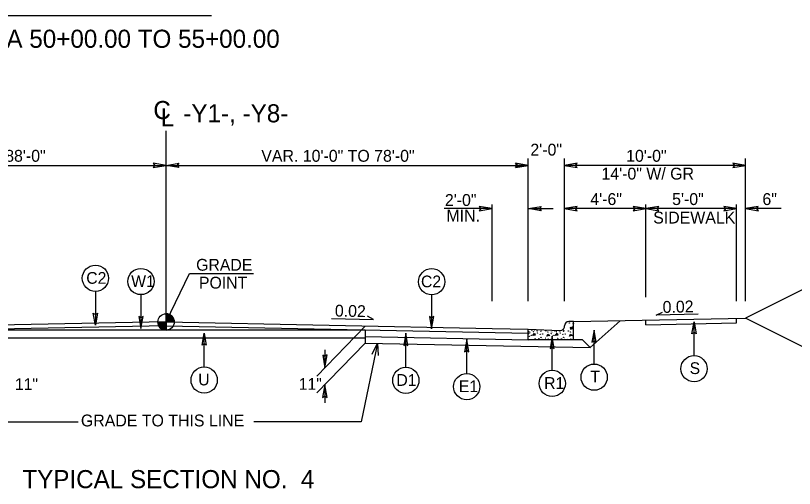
# Model space of a CAD drawing. Extents: x 1901670 to 1902225, y 193498 to 194278.
# Drawn here: x 1902030.87 to 1902073.88, y 193992.53 to 194018.66 of the extents above; entities that cross this region are included whole.
import ezdxf

# ---------------------------------------------------------------- set-up
doc = ezdxf.new("R2010")
doc.units = 0
for name, color, linetype in [('Old_Level_1', 7, 'Continuous'), ('Old_Level_11', 7, 'Continuous'), ('Old_Level_2', 7, 'Continuous'), ('Old_Level_20', 7, 'Continuous'), ('Prop Dimension', 7, 'Continuous'), ('Typical Curb CELL', 7, 'Continuous'), ('Typical Pavement Slope CELL', 7, 'Continuous'), ('Typical Terminator CELL', 7, 'Continuous'), ('Typical Text Grade Point CELL', 7, 'Continuous')]:
    doc.layers.add(name, color=color, linetype=linetype)

# ---------------------------------------------------------------- blocks, each defined once
blk = doc.blocks.new('TERMINATOR')
at = {"layer": 'Typical Terminator CELL'}
blk.add_lwpolyline([(-0.469, 0.081), (0, 0), (-0.471, -0.083), (-0.411, 0)], close=True, dxfattribs=at)

msp = doc.modelspace()

# ---------------------------------------------------------------- linework, layer by layer
at = {"layer": 'Old_Level_1'}
for p, q in [((1902039.184, 194001.732), (1902039.184, 194012.291)), ((1902039.184, 194001.732), (1902039.184, 194002.182)), ((1902066.255, 194002.109), (1902066.588, 194002.276)), ((1902068.57, 194002.158), (1902066.255, 194002.109)), ((1902039.184, 194001.732), (1902019.184, 194001.332)), ((1902038.734, 194001.732), (1902039.184, 194001.732)), ((1902039.183, 194001.282), (1902039.184, 194001.732)), ((1902039.184, 194001.732), (1902039.183, 194001.282)), ((1902039.634, 194001.732), (1902039.184, 194001.732)), ((1902039.184, 194001.732), (1902057.184, 194001.372)), ((1902048.323, 194001.923), (1902050.638, 194001.874)), ((1902050.638, 194001.874), (1902050.305, 194002.041)), ((1902064.265, 194001.8), (1902062.607, 194000.316)), ((1902039.184, 194001.513), (1902019.184, 194001.113)), ((1902028.186, 194001.293), (1902050.182, 194001.293)), ((1902039.184, 194001.513), (1902059.184, 194001.113)), ((1902050.184, 194001.499), (1902047.512, 193998.739)), ((1902050.182, 194001.293), (1902050.182, 194000.564)), ((1902057.184, 194001.372), (1902059.184, 194001.332)), ((1902028.186, 194000.846), (1902050.182, 194000.846)), ((1902050.182, 194000.929), (1902059.184, 194000.749)), ((1902050.182, 194000.564), (1902047.512, 193997.806)), ((1902050.182, 194000.564), (1902062.607, 194000.316)), ((1902062.184, 194000.739), (1902061.684, 194000.749)), ((1902062.184, 194000.739), (1902062.607, 194000.316)), ((1902047.958, 194000.199), (1902047.958, 193999.199)), ((1902047.955, 193998.264), (1902047.955, 193997.264))]:
    msp.add_line(p, q, dxfattribs=at)
for points in [[(1902039.188, 194002.182), (1902039.188, 194002.182), (1902039.188, 194001.732)], [(1902039.197, 194002.182), (1902039.197, 194001.732)], [(1902039.206, 194002.181), (1902039.206, 194001.732)], [(1902039.215, 194002.181), (1902039.215, 194001.732)], [(1902039.224, 194002.18), (1902039.224, 194001.732)], [(1902039.233, 194002.179), (1902039.233, 194001.732)], [(1902039.242, 194002.178), (1902039.242, 194001.732)], [(1902039.251, 194002.177), (1902039.251, 194001.732)], [(1902039.26, 194002.176), (1902039.26, 194001.732)], [(1902039.269, 194002.174), (1902039.269, 194001.732)], [(1902039.278, 194002.172), (1902039.278, 194001.732)], [(1902039.287, 194002.17), (1902039.287, 194001.732)], [(1902039.296, 194002.168), (1902039.296, 194001.732)], [(1902039.305, 194002.165), (1902039.305, 194001.732)], [(1902039.314, 194002.163), (1902039.314, 194001.732)], [(1902039.323, 194002.16), (1902039.323, 194001.732)], [(1902039.332, 194002.157), (1902039.332, 194001.732)], [(1902039.341, 194002.154), (1902039.341, 194001.732)], [(1902039.35, 194002.15), (1902039.35, 194001.732)], [(1902039.359, 194002.146), (1902039.359, 194001.732)], [(1902039.368, 194002.142), (1902039.368, 194001.732)], [(1902039.377, 194002.138), (1902039.377, 194001.732)], [(1902039.386, 194002.134), (1902039.386, 194001.732)], [(1902039.395, 194002.129), (1902039.395, 194001.732)], [(1902039.404, 194002.124), (1902039.404, 194001.732)], [(1902039.413, 194002.119), (1902039.413, 194001.732)], [(1902039.422, 194002.114), (1902039.422, 194001.732)], [(1902039.431, 194002.108), (1902039.431, 194001.732)], [(1902039.44, 194002.102), (1902039.44, 194001.732)], [(1902039.449, 194002.095), (1902039.449, 194001.732)], [(1902039.458, 194002.089), (1902039.458, 194001.732)], [(1902038.736, 194001.732), (1902038.736, 194001.683)], [(1902038.745, 194001.732), (1902038.745, 194001.63)], [(1902038.754, 194001.732), (1902038.754, 194001.598)], [(1902038.763, 194001.732), (1902038.763, 194001.571)], [(1902038.772, 194001.732), (1902038.772, 194001.55)], [(1902038.781, 194001.732), (1902038.781, 194001.531)], [(1902038.79, 194001.732), (1902038.79, 194001.514)], [(1902038.799, 194001.732), (1902038.799, 194001.498)], [(1902038.808, 194001.732), (1902038.808, 194001.484)], [(1902038.817, 194001.732), (1902038.817, 194001.471)], [(1902038.826, 194001.732), (1902038.826, 194001.459)], [(1902038.835, 194001.732), (1902038.835, 194001.448)], [(1902038.844, 194001.732), (1902038.844, 194001.437)], [(1902038.853, 194001.732), (1902038.853, 194001.427)], [(1902038.862, 194001.732), (1902038.862, 194001.417)], [(1902038.871, 194001.732), (1902038.871, 194001.408)], [(1902038.88, 194001.732), (1902038.88, 194001.4)], [(1902038.889, 194001.732), (1902038.889, 194001.392)], [(1902038.898, 194001.732), (1902038.898, 194001.384)], [(1902038.907, 194001.732), (1902038.907, 194001.377)], [(1902038.916, 194001.732), (1902038.916, 194001.37)], [(1902038.925, 194001.732), (1902038.925, 194001.364)], [(1902038.934, 194001.732), (1902038.934, 194001.358)], [(1902038.943, 194001.732), (1902038.943, 194001.352)], [(1902038.952, 194001.732), (1902038.952, 194001.346)], [(1902038.961, 194001.732), (1902038.961, 194001.341)], [(1902038.97, 194001.732), (1902038.97, 194001.336)], [(1902038.979, 194001.732), (1902038.979, 194001.331)], [(1902038.988, 194001.732), (1902038.988, 194001.327)], [(1902038.997, 194001.732), (1902038.997, 194001.323)], [(1902039.006, 194001.732), (1902039.006, 194001.319)], [(1902039.015, 194001.732), (1902039.015, 194001.315)], [(1902039.024, 194001.732), (1902039.024, 194001.311)], [(1902039.033, 194001.732), (1902039.033, 194001.308)], [(1902039.042, 194001.732), (1902039.042, 194001.305)], [(1902039.051, 194001.732), (1902039.051, 194001.302)], [(1902039.06, 194001.732), (1902039.06, 194001.3)], [(1902039.069, 194001.732), (1902039.069, 194001.297)], [(1902039.078, 194001.732), (1902039.078, 194001.295)], [(1902039.087, 194001.732), (1902039.087, 194001.293)], [(1902039.096, 194001.732), (1902039.096, 194001.291)], [(1902039.105, 194001.732), (1902039.105, 194001.289)], [(1902039.114, 194001.732), (1902039.114, 194001.288)], [(1902039.123, 194001.732), (1902039.123, 194001.286)], [(1902039.132, 194001.732), (1902039.132, 194001.285)], [(1902039.141, 194001.732), (1902039.141, 194001.284)], [(1902039.15, 194001.732), (1902039.15, 194001.283)], [(1902039.159, 194001.732), (1902039.159, 194001.283)], [(1902039.168, 194001.732), (1902039.168, 194001.282)], [(1902039.177, 194001.732), (1902039.177, 194001.282), (1902039.177, 194001.282)], [(1902039.467, 194002.082), (1902039.467, 194001.732)], [(1902039.476, 194002.074), (1902039.476, 194001.732)], [(1902039.485, 194002.066), (1902039.485, 194001.732)], [(1902039.494, 194002.058), (1902039.494, 194001.732)], [(1902039.503, 194002.049), (1902039.503, 194001.732)], [(1902039.512, 194002.04), (1902039.512, 194001.732)], [(1902039.521, 194002.03), (1902039.521, 194001.732)], [(1902039.53, 194002.019), (1902039.53, 194001.732)], [(1902039.539, 194002.008), (1902039.539, 194001.732)], [(1902039.548, 194001.996), (1902039.548, 194001.732)], [(1902039.557, 194001.983), (1902039.557, 194001.732)], [(1902039.566, 194001.969), (1902039.566, 194001.732)], [(1902039.575, 194001.954), (1902039.575, 194001.732)], [(1902039.584, 194001.938), (1902039.584, 194001.732)], [(1902039.593, 194001.919), (1902039.593, 194001.732)], [(1902039.602, 194001.898), (1902039.602, 194001.732)], [(1902039.611, 194001.873), (1902039.611, 194001.732)], [(1902039.62, 194001.842), (1902039.62, 194001.732)], [(1902039.629, 194001.796), (1902039.629, 194001.732)], [(1902050.862, 194000.551), (1902049.953, 193996.205)], [(1902050.569, 193999.942), (1902050.862, 194000.551), (1902050.89, 193999.875)], [(1902028.415, 193996.205), (1902034.331, 193996.205)], [(1902049.953, 193996.205), (1902044.037, 193996.205)]]:
    msp.add_lwpolyline(points, dxfattribs=at)
msp.add_circle((1902039.184, 194001.732), 0.45, dxfattribs=at)
for start, end in [(359.9905, 89.9905), (179.9905, 269.9905)]:
    msp.add_arc((1902039.184, 194001.732), 0.45, start, end, dxfattribs=at)
at = {"layer": 'Old_Level_11'}
for p, q in [((1902021.954, 194018.656), (1902041.697, 194018.656)), ((1902035.284, 194003.419), (1902035.284, 194001.545)), ((1902037.795, 194003.238), (1902037.795, 194001.364)), ((1902053.85, 194003.225), (1902053.85, 194001.351)), ((1902068.338, 193999.872), (1902068.338, 194001.746)), ((1902062.823, 193999.406), (1902062.823, 194001.28)), ((1902041.287, 193999.244), (1902041.287, 194001.118)), ((1902052.425, 193999.23), (1902052.425, 194001.104)), ((1902060.507, 193999.061), (1902060.507, 194000.935)), ((1902055.784, 193998.881), (1902055.784, 194000.755))]:
    msp.add_line(p, q, dxfattribs=at)
for points in [[(1902035.4, 194002.217), (1902035.284, 194001.545), (1902035.165, 194002.22), (1902035.284, 194002.134)], [(1902037.68, 194002.036), (1902037.795, 194001.364), (1902037.915, 194002.039), (1902037.795, 194001.953)], [(1902053.734, 194002.023), (1902053.85, 194001.351), (1902053.969, 194002.026), (1902053.85, 194001.941)], [(1902068.223, 194001.074), (1902068.338, 194001.746), (1902068.458, 194001.071), (1902068.338, 194001.156)], [(1902062.938, 194000.609), (1902062.823, 194001.28), (1902062.703, 194000.605), (1902062.823, 194000.691)], [(1902041.172, 194000.447), (1902041.287, 194001.118), (1902041.407, 194000.443), (1902041.287, 194000.529)], [(1902052.541, 194000.432), (1902052.425, 194001.104), (1902052.306, 194000.429), (1902052.425, 194000.514)], [(1902060.622, 194000.263), (1902060.507, 194000.935), (1902060.387, 194000.26), (1902060.507, 194000.345)], [(1902055.9, 194000.084), (1902055.784, 194000.755), (1902055.665, 194000.08), (1902055.784, 194000.166)]]:
    msp.add_lwpolyline(points, close=True, dxfattribs=at)
for centre in [(1902035.284, 194004.144), (1902037.795, 194003.963), (1902053.85, 194003.951), (1902068.338, 193999.146), (1902041.287, 193998.519), (1902052.425, 193998.505), (1902062.823, 193998.681), (1902055.784, 193998.156), (1902060.507, 193998.336)]:
    msp.add_circle(centre, 0.725, dxfattribs=at)
at = {"layer": 'Prop Dimension'}
for p, q in [((1902059.184, 194002.87), (1902059.184, 194010.752)), ((1902059.184, 194002.87), (1902059.184, 194010.712)), ((1902061.184, 194002.87), (1902061.184, 194010.752)), ((1902071.184, 194002.87), (1902071.184, 194010.752)), ((1902019.184, 194010.382), (1902039.184, 194010.382)), ((1902039.184, 194010.382), (1902059.184, 194010.382)), ((1902071.184, 194010.382), (1902061.184, 194010.382)), ((1902057.184, 194002.87), (1902057.184, 194008.219)), ((1902065.684, 194003.091), (1902065.684, 194008.219)), ((1902070.684, 194002.87), (1902070.684, 194008.219)), ((1902057.184, 194007.992), (1902054.538, 194007.992)), ((1902059.184, 194007.992), (1902060.567, 194007.992)), ((1902065.684, 194007.992), (1902061.184, 194007.992)), ((1902070.684, 194007.992), (1902065.684, 194007.992)), ((1902073.149, 194007.992), (1902071.184, 194007.992))]:
    msp.add_line(p, q, dxfattribs=at)
at = {"layer": 'Typical Curb CELL'}
for p, q in [((1902061.684, 194001.749), (1902061.423, 194001.749)), ((1902061.684, 194000.749), (1902061.684, 194001.749)), ((1902059.184, 194000.749), (1902059.184, 194001.332)), ((1902059.184, 194001.332), (1902060.934, 194001.259)), ((1902061.184, 194001.498), (1902061.184, 194001.509)), ((1902061.493, 194001.415), (1902061.51, 194001.325)), ((1902061.647, 194001.371), (1902061.493, 194001.415)), ((1902061.51, 194001.325), (1902061.647, 194001.371)), ((1902059.444, 194000.988), (1902059.531, 194001.108)), ((1902059.565, 194000.995), (1902059.444, 194000.988)), ((1902059.531, 194001.108), (1902059.565, 194000.995)), ((1902060.21, 194000.937), (1902060.272, 194001.052)), ((1902060.376, 194000.977), (1902060.21, 194000.937)), ((1902060.272, 194001.052), (1902060.376, 194000.977)), ((1902060.694, 194000.988), (1902060.78, 194001.108)), ((1902060.814, 194000.995), (1902060.694, 194000.988)), ((1902060.78, 194001.108), (1902060.814, 194000.995)), ((1902061.459, 194000.937), (1902061.521, 194001.052)), ((1902061.624, 194000.977), (1902061.459, 194000.937)), ((1902061.521, 194001.052), (1902061.624, 194000.977)), ((1902061.684, 194000.749), (1902059.184, 194000.749))]:
    msp.add_line(p, q, dxfattribs=at)
for centre in [(1902061.453, 194001.673), (1902059.382, 194001.273), (1902059.525, 194001.29), (1902059.673, 194001.228), (1902059.896, 194001.262), (1902060.153, 194001.233), (1902060.631, 194001.242), (1902060.922, 194001.228), (1902061.145, 194001.262), (1902061.402, 194001.233), (1902061.619, 194001.456), (1902061.67, 194001.639), (1902059.201, 194001.086), (1902059.218, 194001.183), (1902059.258, 194000.943), (1902059.274, 194001.149), (1902059.354, 194000.989), (1902059.479, 194001.188), (1902059.565, 194000.823), (1902059.702, 194001.126), (1902059.77, 194000.8), (1902059.85, 194001.04), (1902059.879, 194001.211), (1902059.885, 194000.886), (1902059.976, 194001.069), (1902060.119, 194000.835), (1902060.273, 194001.183), (1902060.29, 194000.795), (1902060.45, 194001.086), (1902060.467, 194001.183), (1902060.507, 194000.943), (1902060.523, 194001.149), (1902060.603, 194000.989), (1902060.728, 194001.188), (1902060.814, 194000.823), (1902060.951, 194001.126), (1902061.019, 194000.8), (1902061.099, 194001.04), (1902061.128, 194001.211), (1902061.134, 194000.886), (1902061.225, 194001.069), (1902061.368, 194000.835), (1902061.522, 194001.183), (1902061.539, 194000.795), (1902059.195, 194000.777), (1902059.405, 194000.755), (1902059.942, 194000.772), (1902060.444, 194000.777), (1902060.654, 194000.755), (1902061.191, 194000.772)]:
    msp.add_circle(centre, 0.00802, dxfattribs=at)
for centre, start, end in [((1902061.423, 194001.509), 89.9998, 179.9998), ((1902060.944, 194001.498), 267.6154, 359.9998)]:
    msp.add_arc(centre, 0.24, start, end, dxfattribs=at)
at = {"layer": 'Typical Pavement Slope CELL'}
for p, q in [((1902079.141, 194005.917), (1902071.184, 194001.939)), ((1902061.684, 194001.749), (1902071.184, 194001.939)), ((1902065.684, 194001.579), (1902065.684, 194001.829)), ((1902065.684, 194001.579), (1902070.684, 194001.679)), ((1902070.684, 194001.679), (1902070.684, 194001.929)), ((1902079.141, 193997.96), (1902071.184, 194001.939))]:
    msp.add_line(p, q, dxfattribs=at)
at = {"layer": 'Typical Text Grade Point CELL'}
for p, q in [((1902039.184, 194001.732), (1902040.48, 194004.405)), ((1902040.48, 194004.405), (1902044.017, 194004.405))]:
    msp.add_line(p, q, dxfattribs=at)

# ---------------------------------------------------------------- block references
at = {"layer": 'Old_Level_1', "xscale": 1.5, "yscale": -1.5}
for p, rotation in [((1902047.958, 193999.199), -90), ((1902047.955, 193998.264), 90.00000000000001)]:
    msp.add_blockref('TERMINATOR', p, dxfattribs=dict(at, rotation=rotation))
at = {"layer": 'Prop Dimension', "xscale": 1.5}
for p, yscale in [((1902039.184, 194010.382), -1.5), ((1902059.184, 194010.382), -1.5), ((1902059.184, 194010.382), 1.5), ((1902071.184, 194010.382), -1.5), ((1902057.184, 194007.992), -1.5), ((1902065.684, 194007.992), -1.5), ((1902070.684, 194007.992), -1.5)]:
    msp.add_blockref('TERMINATOR', p, dxfattribs=dict(at, yscale=yscale))
at = {"layer": 'Prop Dimension', "xscale": 1.5, "rotation": 180}
for p, yscale in [((1902039.184, 194010.382), 1.5), ((1902061.184, 194010.382), -1.5), ((1902059.184, 194007.992), 1.5), ((1902061.184, 194007.992), -1.5), ((1902065.684, 194007.992), -1.5), ((1902071.184, 194007.992), -1.5)]:
    msp.add_blockref('TERMINATOR', p, dxfattribs=dict(at, yscale=yscale))

# ---------------------------------------------------------------- texts
at = {"layer": 'Old_Level_1'}
for s, height, p in [('11"', 0.6491, (1902030.837, 193997.97)), ('11"', 0.6491, (1902046.511, 193997.983)), ('GRADE TO THIS LINE', 0.656, (1902034.482, 193995.959))]:
    msp.add_text(s, height=height, dxfattribs=at).set_placement(p)
at = {"layer": 'Old_Level_11'}
for s, p in [('-L- STA 50+00.00 TO 55+00.00', (1902026.654, 194016.875)), ('TYPICAL SECTION NO.  4', (1902031.248, 193992.548))]:
    msp.add_text(s, height=1, dxfattribs=at).set_placement(p)
at = {"layer": 'Old_Level_2'}
msp.add_text('C', height=1, dxfattribs=at).set_placement((1902038.482, 194012.937))
for s, height, rotation, p in [('-Y1-, -Y8-', 1, 359.9469, (1902040.139, 194012.762)), ('L', 1, 359.9469, (1902038.884, 194012.533)), ('0.02', 0.656, 358.8084, (1902048.5, 194002.03)), ('0.02', 0.656, 1.1916, (1902066.61, 194002.228))]:
    msp.add_text(s, height=height, rotation=rotation, dxfattribs=at).set_placement(p)
at = {"layer": 'Old_Level_20'}
for s, height, p in [('C2', 0.6491, (1902034.778, 194003.838)), ('W1', 0.6491, (1902037.258, 194003.657)), ('C2', 0.6491, (1902053.261, 194003.644)), ('S', 0.649, (1902068.095, 193998.853)), ('U', 0.649, (1902040.96, 193998.226)), ('D1', 0.6491, (1902051.903, 193998.201)), ('R1', 0.6491, (1902060.061, 193998.032)), ('T', 0.649, (1902062.612, 193998.388)), ('E1', 0.6491, (1902055.35, 193997.852))]:
    msp.add_text(s, height=height, dxfattribs=at).set_placement(p)
at = {"layer": 'Prop Dimension'}
for s, p in [('2\'-0" ', (1902059.301, 194010.921)), ('VAR. 10\'-0" TO 88\'-0"', (1902024.07, 194010.58)), ('VAR. 10\'-0" TO 78\'-0"', (1902044.443, 194010.58)), ('10\'-0" ', (1902064.589, 194010.58)), ('14\'-0" W/ GR ', (1902063.226, 194009.597)), ('2\'-0"', (1902054.58, 194008.138)), ('4\'-6" ', (1902062.61, 194008.19)), ('5\'-0" ', (1902067.129, 194008.19)), ('6" ', (1902072.115, 194008.19)), ('MIN. ', (1902054.666, 194007.278)), ('SIDEWALK', (1902066.083, 194007.169))]:
    msp.add_text(s, height=0.656, dxfattribs=at).set_placement(p)
at = {"layer": 'Typical Text Grade Point CELL'}
for s, p in [('GRADE', (1902040.844, 194004.561)), ('POINT', (1902041.001, 194003.573))]:
    msp.add_text(s, height=0.6525, dxfattribs=at).set_placement(p)

doc.saveas('drawing.dxf')
